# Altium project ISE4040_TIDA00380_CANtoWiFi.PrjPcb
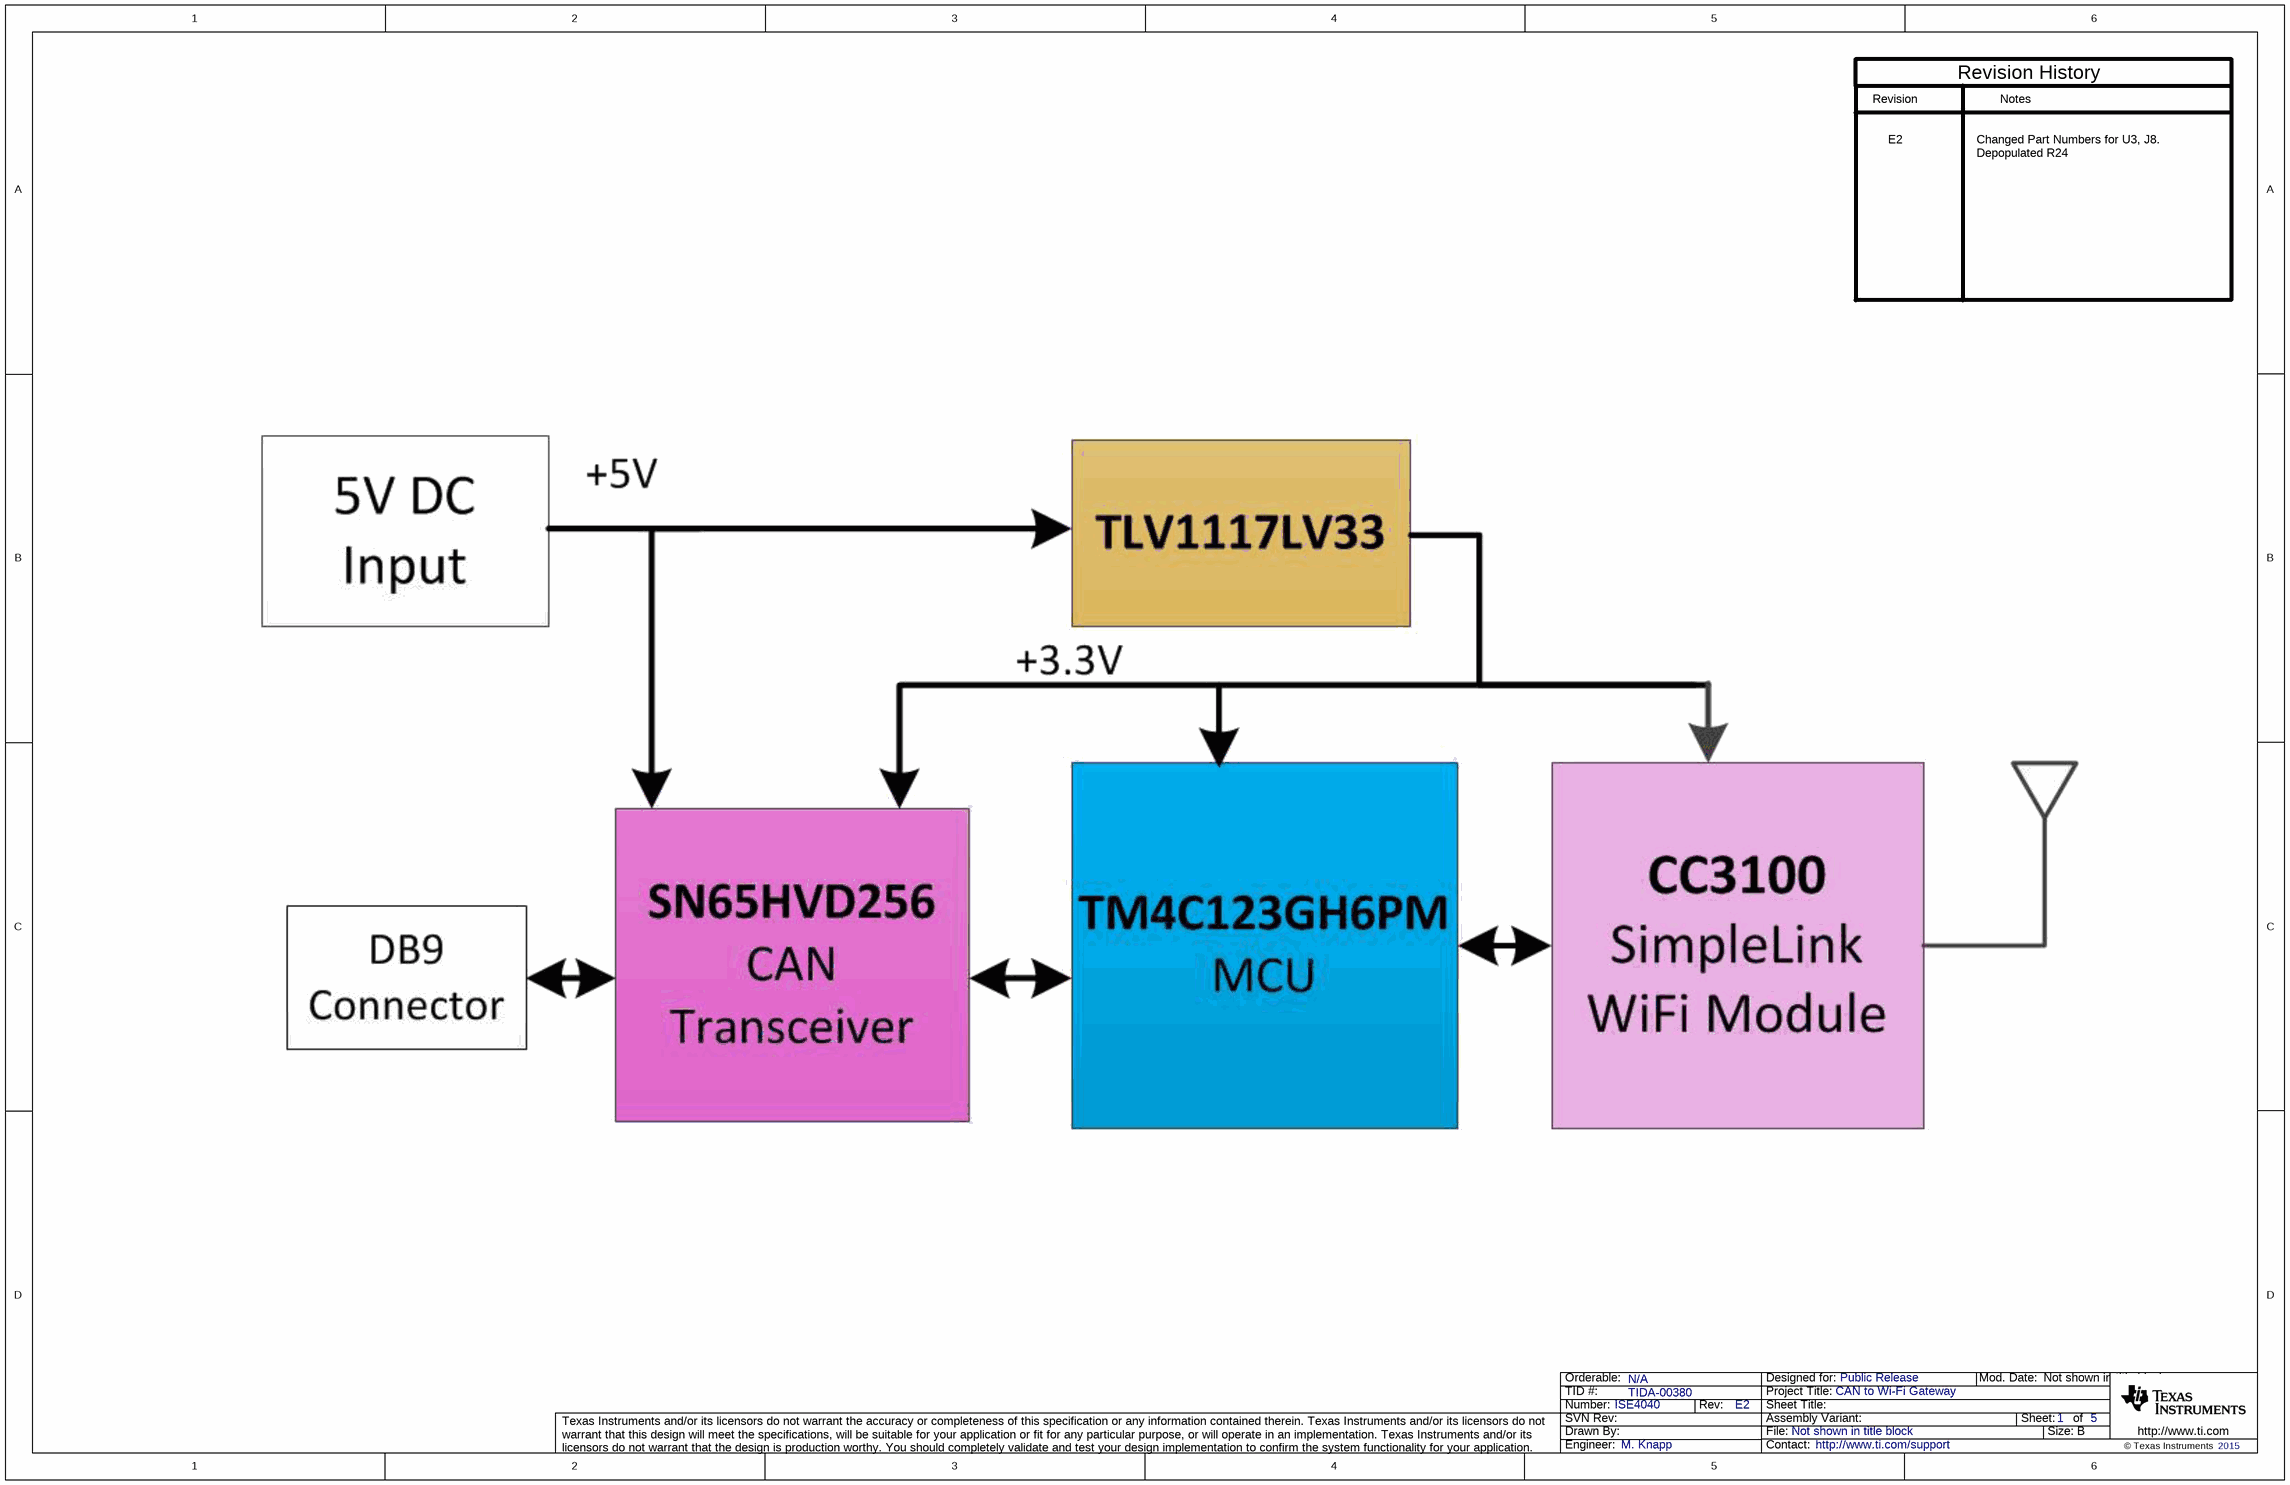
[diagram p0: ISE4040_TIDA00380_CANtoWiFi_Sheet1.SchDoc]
CopyrightYear: 2015; EVM_Orderable: N/A; PCB_Layout: Krypton Solution LLC; PCB_Rev: E2; PRJ_Customer: Public Release; PRJ_Engineer: M. Knapp; PRJ_Number: ISE4040; PRJ_Title: CAN to Wi-Fi Gateway; SCH_Rev: E2; TechSupport: http://www.ti.com/support; TID: TIDA-00380
5 sheets, 120 parts. Net scope: global (net labels, ports and power ports of the same name join across sheets).
Board file: ISE4040_TIDA00380_CANtoWiFi.PcbDoc
Sheets:
  ISE4040_TIDA00380_CANtoWiFi_Sheet1.SchDoc
  ISE4040_TIDA00380_CANtoWiFi_Sheet2.SchDoc
  ISE4040_TIDA00380_CANtoWiFi_Sheet3.SchDoc
  ISE4040_TIDA00380_CANtoWiFi_Sheet4.SchDoc
  ISE4040_TIDA00380_CANtoWiFi_Sheet5.SchDoc

## Sheet ISE4040_TIDA00380_CANtoWiFi_Sheet1.SchDoc
size 431 x 279 mm; Date: Not shown in title block; ApprovedBy: Not shown in title block; CheckedBy: Not shown in title block; Author: Not shown in title block; CompanyName: Not shown in title block; Engineer: Not shown in title block; Organization: Not shown in title block; Address1: Not shown in title block; Address2: Not shown in title block; Address3: Not shown in title block; Address4: Not shown in title block; DocumentNumber: 1; Revision: Use project parameter SCH_Rev; SheetNumber: 1; SheetTotal: 5; PageSetup: Record=PageOptions¦CenterHorizontal=True¦CenterVertical=True¦PrintScale=1.00¦XCorrection=1.00¦YCorrection=1.00¦PrintKind=0¦BorderSize=5000000¦LeftOffset=0¦BottomOffset=0¦Orientation=2¦PaperLength=1000¦PaperWidth=1000¦Scale=100¦PaperSource=15¦PrintQuality=600¦MediaType=1¦DitherType=10¦PaperKind=Letter¦PrintScaleMode=1

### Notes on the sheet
- Revision
- Notes
- Revision History
- E2
- Changed Part Numbers for U3, J8.
- Depopulated R24

## Sheet ISE4040_TIDA00380_CANtoWiFi_Sheet2.SchDoc
size 431 x 279 mm; Date: Not shown in title block; ApprovedBy: Not shown in title block; CheckedBy: Not shown in title block; Author: Not shown in title block; CompanyName: Not shown in title block; Engineer: Not shown in title block; Organization: Not shown in title block; Address1: Not shown in title block; Address2: Not shown in title block; Address3: Not shown in title block; Address4: Not shown in title block; DocumentNumber: 2; Revision: Use project parameter SCH_Rev; SheetNumber: 2; SheetTotal: 5; PageSetup: Record=PageOptions¦CenterHorizontal=True¦CenterVertical=True¦PrintScale=1.00¦XCorrection=1.00¦YCorrection=1.00¦PrintKind=0¦BorderSize=5000000¦LeftOffset=0¦BottomOffset=0¦Orientation=2¦PaperLength=1000¦PaperWidth=1000¦Scale=100¦PaperSource=15¦PrintQuality=600¦MediaType=1¦DitherType=10¦PaperKind=Letter¦PrintScaleMode=1
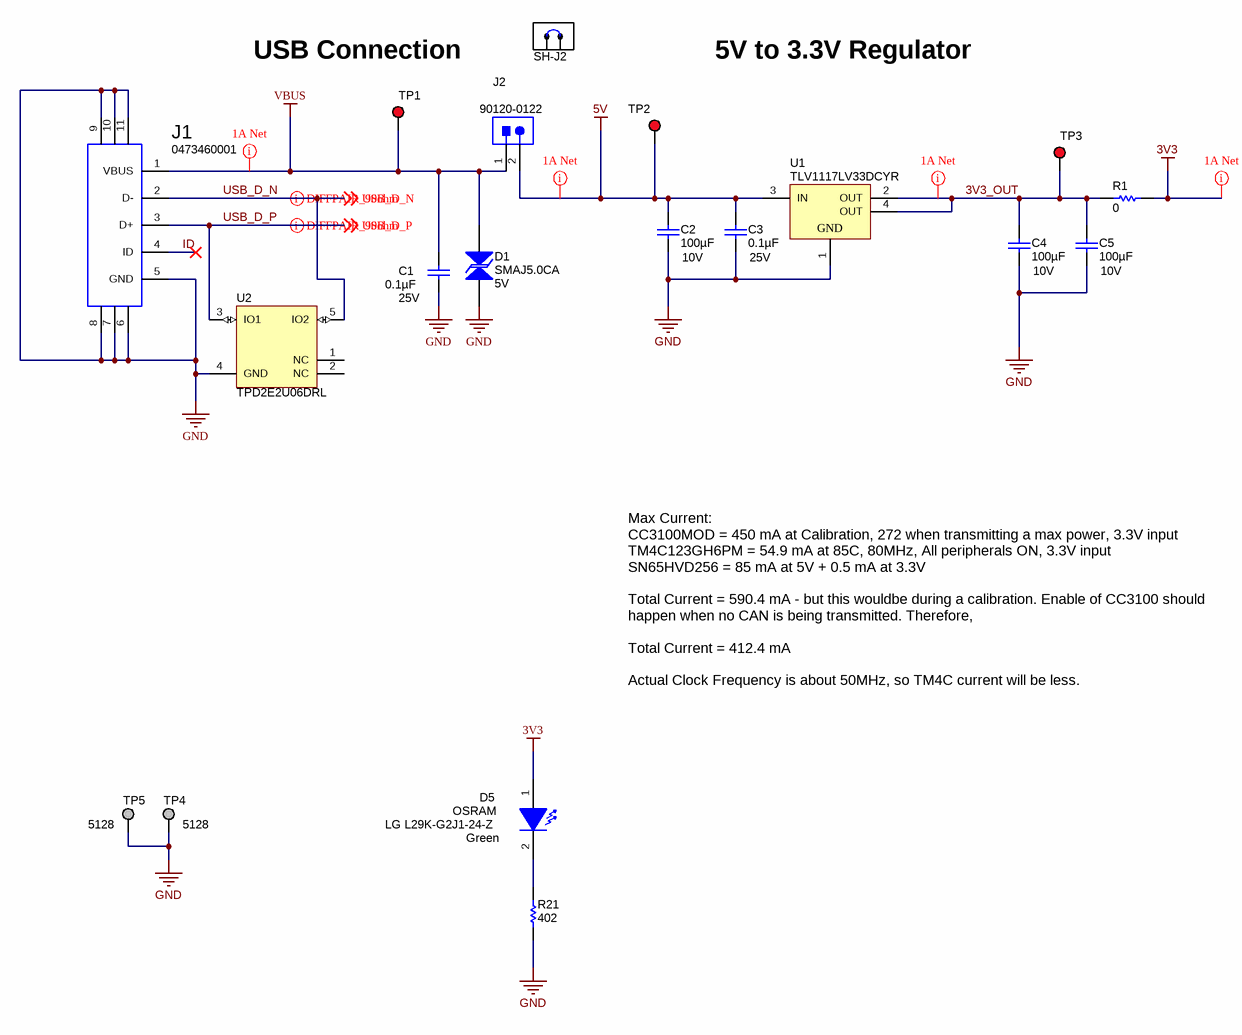
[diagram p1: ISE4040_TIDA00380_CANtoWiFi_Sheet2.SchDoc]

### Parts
C1  ValueDisplayed: 0.1µF  Value2: 25V  [0603]  (hidden comment: 06033C104JAT2A)
C2  ValueDisplayed: 100µF  Value2: 10V  [1210_280]  (hidden comment: C1210C107M8PACTU)
C3  ValueDisplayed: 0.1µF  Value2: 25V  [0603]  (hidden comment: 06033C104JAT2A)
C4  ValueDisplayed: 100µF  Value2: 10V  [1210_280]  (hidden comment: C1210C107M8PACTU)
C5  ValueDisplayed: 100µF  Value2: 10V  [1210_280]  (hidden comment: C1210C107M8PACTU)
D1  SMAJ5.0CA  value 5V  [SMA]
D5  value Green  Manufacturer: OSRAM  [LG L29K_GREEN]  (hidden comment: LG L29K-G2J1-24-Z)
J1  0473460001  [CONN_47346-0001]
J2  90120-0122  [CONN_90120-0122]
R1  ValueDisplayed: 0  [2010]  (hidden comment: CRCW20100000Z0EF)
R21  ValueDisplayed: 402  [0402]  (hidden comment: CRCW0402402RFKED)
SH-J2  2SN-BK-G  [2SN-BK-G]  (value not drawn)
TP1  5000  [Keystone5000]  (value not drawn)
TP2  5000  [Keystone5000]  (value not drawn)
TP3  5000  [Keystone5000]  (value not drawn)
TP4  5128  [Keystone5128]
TP5  5128  [Keystone5128]
U1  TLV1117LV33DCYR  [DCY0004A_N]
U2  TPD2E2U06DRL  [DRL0005A]

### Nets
3V3: D5.1(A) R1.2
5V: C2.1 C3.1 J2.2 TP2.1 U1.3(IN)
GND: C1.2 C2.2 C3.2 C4.2 C5.2 D1.2 J1.5(GND) J1.6 J1.7 J1.8 J1.9 J1.10 J1.11 R21.1 TP4.1 TP5.1 U1.1(GND) U2.4(GND)
VBUS: C1.1 D1.1 J1.1(VBUS) J2.1 TP1.1
3V3_OUT: C4.1 C5.1 R1.1 TP3.1 U1.2(OUT) U1.4(OUT)
ID: J1.4(ID)
USB_D_N: J1.2(D-) U2.5(IO2) ; off-sheet USB_D_N
USB_D_P: J1.3(D+) U2.3(IO1) ; off-sheet USB_D_P
NetD5_2: D5.2(K) R21.2

Not connected (* = marked no-connect by the designer): U2 1(NC) 2(NC)

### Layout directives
rule Width Constraint [Pref Width = 25mil    Min Width = 5mil    Max Width = 100mil]: 3V3, 3V3_OUT, 5V, VBUS
differential pair: USB_D_N, USB_D_P

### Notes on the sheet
- (near TP1) USB Connection
- 5V to 3.3V Regulator
- Max Current:
  CC3100MOD = 450 mA at Calibration, 272 when transmitting a max power, 3.3V input
  TM4C123GH6PM = 54.9 mA at 85C, 80MHz, All peripherals ON, 3.3V input
  SN65HVD256 = 85 mA at 5V + 0.5 mA at 3.3V
  Total Current = 590.4 mA - but this wouldbe during a calibration. Enable of CC3100 should
  happen when no CAN is being transmitted. Therefore,
  Total Current = 412.4 mA
  Actual Clock Frequency is about 50MHz, so TM4C current will be less.

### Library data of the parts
C1 = 06033C104JAT2A: CAP, CERM, 0.1 µF, 25 V, +/- 5%, X7R, 0603; Manufacturer: AVX; Polarized: N; CompType: Capacitor; Value: 0.1uF; U/M: EA; Cap_F: 0.0000001; Tolerance_%: 5; Value1: 0.05 ohm; VDC_V: 25; ESR_ohm: 0.05; TaMin_C: -55; TaMax_C: 125
C2 C4 C5 = C1210C107M8PACTU: CAP, CERM, 100 µF, 10 V, +/- 20%, X5R, 1210; Manufacturer: Wurth Elektronik; Polarized: N; CompType: Capacitor; Value: 100uF; U/M: EA; Cap_F: 0.0001; Tolerance_%: 20; Value1: Unknown; VDC_V: 10; TaMin_C: -55; TaMax_C: 85; Cap_Case: 1210
C3 = 06033C104JAT2A: CAP, CERM, 0.1 µF, 25 V, +/- 5%, X7R, 0603; Manufacturer: AVX; Polarized: N; CompType: Capacitor; Value: 0.1uF; U/M: EA; Cap_F: 0.0000001; Tolerance_%: 5; ESR_ohm: 0.05; Value1: 0.05 ohm; VDC_V: 25; TaMin_C: -55; TaMax_C: 125
D1 = SMAJ5.0CA: Diode, TVS, Bi, 5 V, 400 W, SMA; Manufacturer: Littelfuse; U/M: EA; Power_W: 400; Vr_V: 5; Value1: 400W; RJA_CperW: 120
D5 = LG L29K-G2J1-24-Z: LED, Green, SMD; Vf_V: 1.7; Value2: 1.7V; Io_A: 0.002; Tjmax_C: 110; Value1: W; U/M: EA
J1 = 0473460001: Connector, Receptacle, Micro-USB Type B, R/A, Bottom Mount SMT; Manufacturer: Molex; SymbolCreator: a0411947; U/M: EA
J2 = 90120-0122: Header, 100mil, 2x1, Tin, TH; Manufacturer: Molex; SymbolCreator: a0412235; U/M: EA
R1 = CRCW20100000Z0EF: RES, 0, 5%, 0.75 W, 2010; Manufacturer: Vishay-Dale; CompType: Resistor; Value: 0; Value_Code: 0000; Tolerance_%: 5; Power_W: 0.75; Value2: 0.75W; TempCo: ppm/C; EIA_Code: E24; U/M: EA
R21 = CRCW0402402RFKED: RES, 402, 1%, 0.063 W, 0402; Manufacturer: Vishay-Dale; CompType: Resistor; Value: 402; Value_Code: 402R; Tolerance_%: 1; Power_W: 0.063; Value2: 0.063W; VDC_V: 50; TempCo: 100 ppm/C; EIA_Code: E96; U/M: EA
SH-J2 = 2SN-BK-G: Shunt, 2mm, Gold plated, Black; Manufacturer: Samtec; Value: 1x2; Note: You can "mate" this to a header by matching the designator.  i.e. use SH-J3 for header J3
TP1-TP3 = 5000: Test Point, Miniature, Red, TH; Manufacturer: Keystone; CompType: Test Point Loop; U/M: EA
TP4 TP5 = 5128: Test Point, Multipurpose, Grey, TH; Manufacturer: Keystone; CompType: Test Point Loop; U/M: EA; SymbolCreator: a0412235
U1 = TLV1117LV33DCYR: Single Output LDO, 1 A, Fixed 3.3 V Output, 2 to 5.5 V Input, 4-pin SOT-223 (DCY), -40 to 125 degC, Green (RoHS & no Sb/Br); Manufacturer: Texas Instruments; Alternate Manufacturer: None; Alternate PartNumber: Equivalent; Accuracy(%): 2; Fixed Output Options(V): 3.3; Iout(Max)(A): 1; Iq(Typ)(mA): 0.05; SubFamily: Single Channel LDO; Vdo(Typ)(mV): 1200; Vin(Max)(V): 5.5
U2 = TPD2E2U06DRL: DUAL CHANNEL HIGH SPEED ESD PROTECTION DEVICE, DRL0005A; Manufacturer: Texas Instruments; SymbolCreator: a0411947; CompType: IC; U/M: EA

## Sheet ISE4040_TIDA00380_CANtoWiFi_Sheet3.SchDoc
size 431 x 279 mm; Date: Not shown in title block; ApprovedBy: Not shown in title block; CheckedBy: Not shown in title block; Author: Not shown in title block; CompanyName: Not shown in title block; Engineer: Not shown in title block; Organization: Not shown in title block; Address1: Not shown in title block; Address2: Not shown in title block; Address3: Not shown in title block; Address4: Not shown in title block; DocumentNumber: 3; Revision: Use project parameter SCH_Rev; SheetNumber: 3; SheetTotal: 5; PageSetup: Record=PageOptions¦CenterHorizontal=True¦CenterVertical=True¦PrintScale=1.00¦XCorrection=1.00¦YCorrection=1.00¦PrintKind=0¦BorderSize=5000000¦LeftOffset=0¦BottomOffset=0¦Orientation=2¦PaperLength=1000¦PaperWidth=1000¦Scale=100¦PaperSource=15¦PrintQuality=600¦MediaType=1¦DitherType=10¦PaperKind=Letter¦PrintScaleMode=1
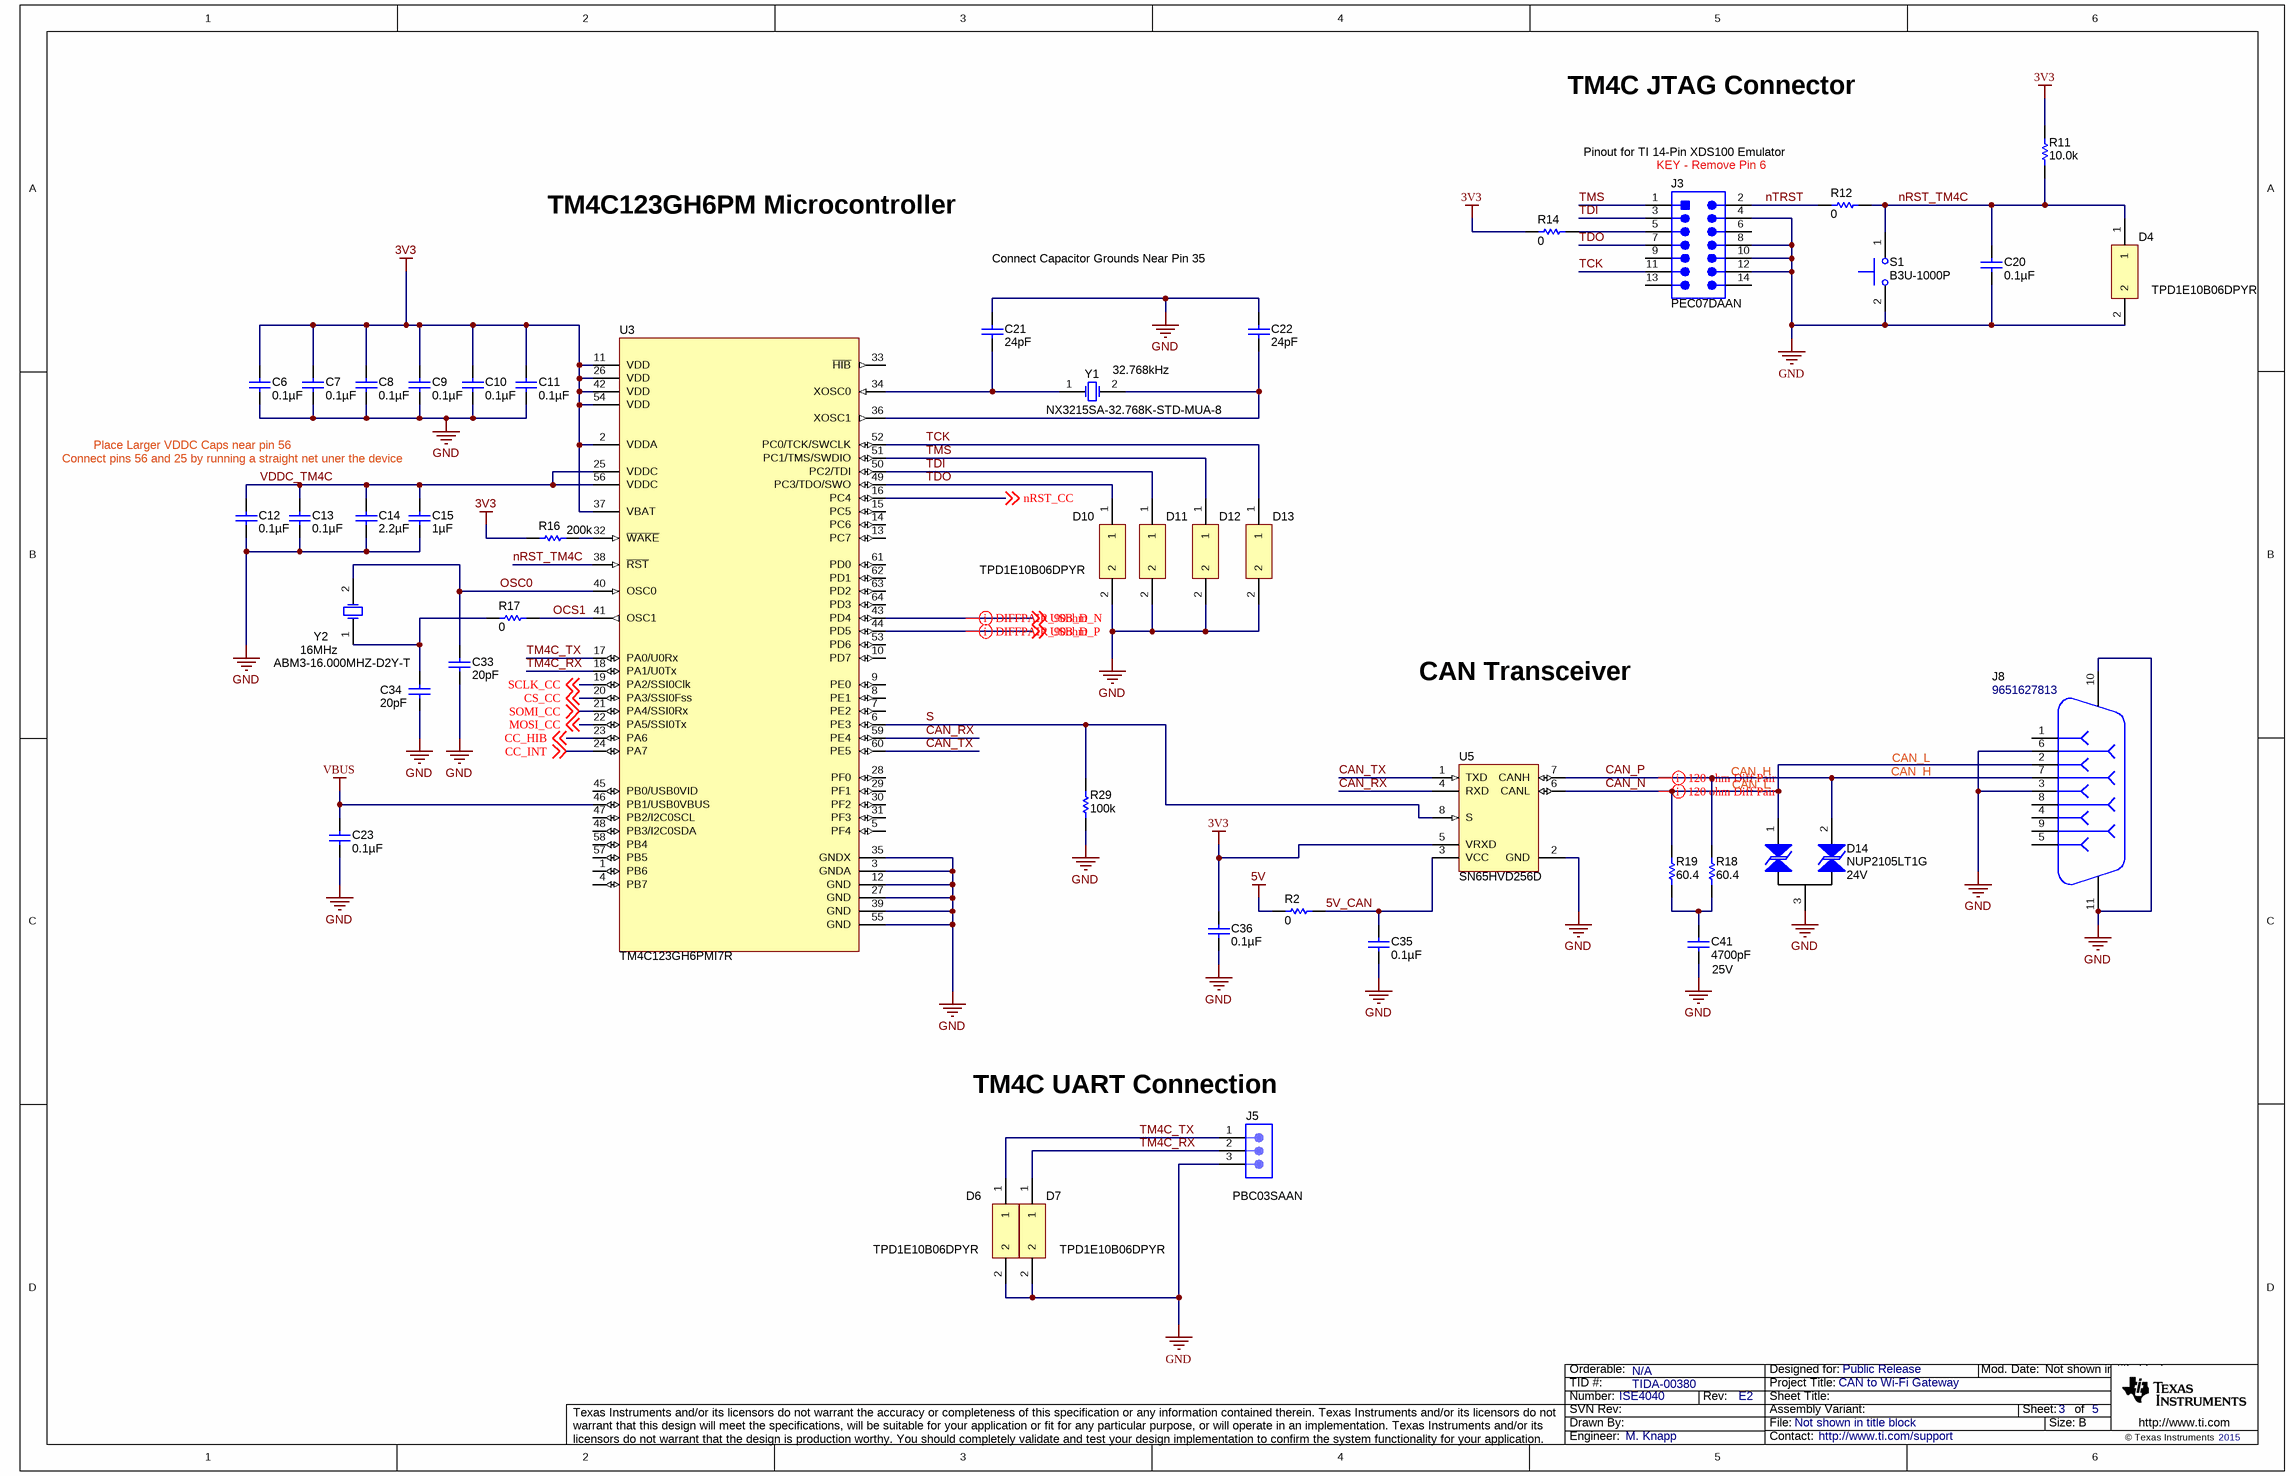
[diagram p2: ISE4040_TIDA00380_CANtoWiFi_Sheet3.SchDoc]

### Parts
C6  ValueDisplayed: 0.1µF  [0402]  (hidden comment: GRM155R71C104KA88D)
C7  ValueDisplayed: 0.1µF  [0402]  (hidden comment: GRM155R71C104KA88D)
C8  ValueDisplayed: 0.1µF  [0402]  (hidden comment: GRM155R71C104KA88D)
C9  ValueDisplayed: 0.1µF  [0402]  (hidden comment: GRM155R71C104KA88D)
C10  ValueDisplayed: 0.1µF  [0402]  (hidden comment: GRM155R71C104KA88D)
C11  ValueDisplayed: 0.1µF  [0402]  (hidden comment: GRM155R71C104KA88D)
C12  ValueDisplayed: 0.1µF  [0402]  (hidden comment: GRM155R71C104KA88D)
C13  ValueDisplayed: 0.1µF  [0402]  (hidden comment: GRM155R71C104KA88D)
C14  ValueDisplayed: 2.2µF  [0805_HV]  (hidden comment: C0805C225K8RACTU)
C15  ValueDisplayed: 1µF  [0603]  (hidden comment: GRM188R71C105KA12D)
C20  ValueDisplayed: 0.1µF  [0402]  (hidden comment: GRM155R71C104KA88D)
C21  ValueDisplayed: 24pF  [0402]  (hidden comment: GRM1555C1H240JA01D)
C22  ValueDisplayed: 24pF  [0402]  (hidden comment: GRM1555C1H240JA01D)
C23  ValueDisplayed: 0.1µF  [0402]  (hidden comment: GRM155R71C104KA88D)
C33  ValueDisplayed: 20pF  [0603]  (hidden comment: GRM1885C1H200JA01D)
C34  ValueDisplayed: 20pF  [0603]  (hidden comment: GRM1885C1H200JA01D)
C35  ValueDisplayed: 0.1µF  [0402]  (hidden comment: GRM155R71C104KA88D)
C36  ValueDisplayed: 0.1µF  [0402]  (hidden comment: GRM155R71C104KA88D)
C41  ValueDisplayed: 4700pF  Value2: 25V  [0402]  (hidden comment: C1005X7R1E472K)
D4  TPD1E10B06DPYR  [DPY0002A]
D6  TPD1E10B06DPYR  [DPY0002A]
D7  TPD1E10B06DPYR  [DPY0002A]
D10  TPD1E10B06DPYR  [DPY0002A]
D11  TPD1E10B06DPYR  [DPY0002A]  (value not drawn)
D12  TPD1E10B06DPYR  [DPY0002A]  (value not drawn)
D13  TPD1E10B06DPYR  [DPY0002A]  (value not drawn)
D14  NUP2105LT1G  value 24V  [SOT-23]
J3  PEC07DAAN  [CONN_PEC07DAAN]
J5  PBC03SAAN  [PBC03SAAN]
J8  9651627813  [Harting_09 65 162 6810]
R2  ValueDisplayed: 0  [0402]  (hidden comment: CRCW04020000Z0ED)
R11  ValueDisplayed: 10.0k  [0402]  (hidden comment: CRCW040210K0FKED)
R12  ValueDisplayed: 0  [0402]  (hidden comment: CRCW04020000Z0ED)
R14  ValueDisplayed: 0  [0402]  (hidden comment: CRCW04020000Z0ED)
R16  ValueDisplayed: 200k  [0402]  (hidden comment: CRCW0402200KFKED)
R17  ValueDisplayed: 0  [0402]  (hidden comment: CRCW04020000Z0ED)
R18  ValueDisplayed: 60.4  [0603]  (hidden comment: CRCW060360R4FKEA)
R19  ValueDisplayed: 60.4  [0603]  (hidden comment: CRCW060360R4FKEA)
R29  ValueDisplayed: 100k  [0402]  (hidden comment: CRCW0402100KFKED)
S1  B3U-1000P  [SW_B3U-1000P]
U3  TM4C123GH6PMI7R  [PM0064A_N]
U5  SN65HVD256D  [D0008A_L]
Y1  NX3215SA-32.768K-STD-MUA-8  Frequency: 32.768kHz  [XTAL_NX3215SA]
Y2  ABM3-16.000MHZ-D2Y-T  Frequency: 16MHz  [XTAL_ABM3]

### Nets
3V3: C6.1 C7.1 C8.1 C9.1 C10.1 C11.1 C36.1 R11.2 R14.2 R16.1 U3.2(VDDA) U3.11(VDD) U3.26(VDD) U3.37(VBAT) U3.42(VDD) U3.54(VDD) U5.5(VRXD)
5V: R2.2
GND: C6.2 C7.2 C8.2 C9.2 C10.2 C11.2 C12.2 C13.2 C14.2 C15.2 C20.2 C21.1 C22.1 C23.2 C33.2 C34.2 C35.2 C36.2 C41.2 D4.2 D6.2 D7.2 D10.2 D11.2 D12.2 D13.2 D14.3 J3.4 J3.8 J3.10 J3.12 J5.3 J8.3 J8.6 J8.10 J8.11 R29.1 S1.2 U3.3(GNDA) U3.12(GND) U3.27(GND) U3.35(GNDX) U3.39(GND) U3.55(GND) U5.2(GND)
VBUS: C23.1 U3.46(PB1/USB0VBUS)
5V_CAN: C35.1 R2.1 U5.3(VCC)
CAN_N: D14.1 J8.2 R19.2 U5.6(CANL)
CAN_P: D14.2 J8.7 R18.2 U5.7(CANH)
CAN_RX: U3.59(PE4) U5.4(RXD)
CAN_TX: U3.60(PE5) U5.1(TXD)
CC_HIB: U3.23(PA6) ; off-sheet CC_HIB
CC_INT: U3.24(PA7) ; off-sheet CC_INT
CS_CC: U3.20(PA3/SSI0Fss) ; off-sheet CS_CC
MOSI_CC: U3.22(PA5/SSI0Tx) ; off-sheet MOSI_CC
nRST_CC: U3.16(PC4) ; off-sheet nRST_CC
nRST_TM4C: C20.1 D4.1 R11.1 R12.1 S1.1 U3.38(~{RST})
nTRST: J3.2 R12.2
OCS1: R17.2 U3.41(OSC1)
OSC0: C33.1 U3.40(OSC0) Y2.2(OSC2)
S: R29.2 U3.6(PE3) U5.8(S)
SCLK_CC: U3.19(PA2/SSI0Clk) ; off-sheet SCLK_CC
SOMI_CC: U3.21(PA4/SSI0Rx) ; off-sheet SOMI_CC
TCK: D13.1 J3.11 U3.52(PC0/TCK/SWCLK)
TDI: D11.1 J3.3 U3.50(PC2/TDI)
TDO: D10.1 J3.7 U3.49(PC3/TDO/SWO)
TM4C_RX: D7.1 J5.2 U3.18(PA1/U0Tx)
TM4C_TX: D6.1 J5.1 U3.17(PA0/U0Rx)
TMS: D12.1 J3.1 U3.51(PC1/TMS/SWDIO)
USB_D_N: U3.43(PD4) ; off-sheet USB_D_N
USB_D_P: U3.44(PD5) ; off-sheet USB_D_P
VDDC_TM4C: C12.1 C13.1 C14.1 C15.1 U3.25(VDDC) U3.56(VDDC)
NetC21_2: C21.2 U3.34(XOSC0) Y1.1(OSC1)
NetC22_2: C22.2 U3.36(XOSC1) Y1.2(OSC2)
NetC34_1: C34.1 R17.1 Y2.1(OSC1)
NetC41_1: C41.1 R18.1 R19.1
NetJ3_5: J3.5 R14.1
NetR16_2: R16.2 U3.32(~{WAKE})

Not connected (* = marked no-connect by the designer): J3 6 9 13 14; J8 1 4 5 8 9; U3 1(PB6) 4(PB7) 5(PF4) 7(PE2) 8(PE1) 9(PE0) 10(PD7) 13(PC7) 14(PC6) 15(PC5) 28(PF0) 29(PF1) 30(PF2) 31(PF3) 33(~{HIB}) 45(PB0/USB0VID) 47(PB2/I2C0SCL) 48(PB3/I2C0SDA) 53(PD6) 57(PB5) 58(PB4) 61(PD0) 62(PD1) 63(PD2) 64(PD3)

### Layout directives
differential pair: CAN_N, CAN_P, USB_D_N, USB_D_P

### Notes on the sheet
- TM4C JTAG Connector
- Pinout for TI 14-Pin XDS100 Emulator
- (near J3) KEY - Remove Pin 6
- TM4C123GH6PM Microcontroller
- Connect Capacitor Grounds Near Pin 35
- Place Larger VDDC Caps near pin 56
- Connect pins 56 and 25 by running a straight net uner the device
- CAN Transceiver
- CAN_L
- CAN_H
- (near J5) TM4C UART Connection

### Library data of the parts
C6-C13 C20 C23 C35 C36 = GRM155R71C104KA88D: CAP, CERM, 0.1 µF, 16 V, +/- 10%, X7R, 0402; Manufacturer: MuRata; Polarized: N; CompType: Capacitor; Value: 0.1uF; U/M: EA; Cap_F: 0.0000001; Tolerance_%: 10; Value1: Unknown; VDC_V: 16; Value2: 16V; TaMin_C: -55; TaMax_C: 125
C14 = C0805C225K8RACTU: CAP, CERM, 2.2 µF, 10 V, +/- 10%, X7R, 0805; Manufacturer: Kemet; Polarized: N; CompType: Capacitor; Value: 2.2uF; U/M: EA; Cap_F: 0.0000022; Tolerance_%: 10; ESR_ohm: 0.008; Value1: 0.008 ohm; Value2: 10V; IRMS_A: 15.55; TaMin_C: -55; TaMax_C: 125; Cap_Case: 0805
C15 = GRM188R71C105KA12D: CAP, CERM, 1 µF, 16 V, +/- 10%, X7R, 0603; Manufacturer: MuRata; Polarized: N; CompType: Capacitor; Value: 1uF; U/M: EA; Cap_F: 0.000001; Tolerance_%: 10; ESR_ohm: 0.011; Value1: 0.011 ohm; VDC_V: 16; Value2: 16V; TaMin_C: -55; TaMax_C: 125
C21 C22 = GRM1555C1H240JA01D: CAP, CERM, 24 pF, 50 V, +/- 5%, C0G/NP0, 0402; Manufacturer: MuRata; Polarized: N; CompType: Capacitor; Value: 24pF; U/M: EA; Cap_F: 0.000000000024; Tolerance_%: 5; Value1: Unknown; VDC_V: 50; Value2: 50V; TaMin_C: -55; TaMax_C: 125
C33 C34 = GRM1885C1H200JA01D: CAP, CERM, 20 pF, 50 V, +/- 5%, C0G/NP0, 0603; Manufacturer: MuRata; Polarized: N; CompType: Capacitor; Value: 20pF; U/M: EA; Cap_F: 0.00000000002; Tolerance_%: 5; Value1: Unknown; VDC_V: 50; Value2: 50V; TaMin_C: -55; TaMax_C: 125
C41 = C1005X7R1E472K: CAP, CERM, 4700 pF, 25 V, +/- 10%, X7R, 0402; Manufacturer: TDK; Polarized: N; CompType: Capacitor; Value: 4700pF; U/M: EA; Cap_F: 0.0000000047; Tolerance_%: 10; ESR_ohm: 0.0826; Value1: 0.0826 ohm; VDC_V: 25; TaMin_C: -55; TaMax_C: 125
D4 D6 D7 D10-D13 = TPD1E10B06DPYR: ESD in 0402 Package with 10 pF Capacitance and 6 V Breakdown, 1 Channel, -40 to +125 degC, 2-pin X2SON (DPY), Green (RoHS & no Sb/Br); Manufacturer: Texas Instruments; Alternate Manufacturer: None; Alternate PartNumber: Equivalent; Breakdown Voltage(Min)(V): 6; Eco-Plan: TBD; IEC 61000-4-2 Air-Gap(+/- kV): 30; IO Capacitance(Typ)(pF): 10; SubFamily: ESD Solution
D14 = NUP2105LT1G: Diode, TVS, Bi, 24 V, 350 W, SOT-23; Manufacturer: ON Semiconductor; SymbolCreator: a0411947; U/M: EA; Power_W: 350; Vr_V: 24; Value1: 350W
J3 = PEC07DAAN: Header, 100mil, 7x2, Tin, TH; Manufacturer: Sullins Connector Solutions; SymbolCreator: a0412235; U/M: EA
J5 = PBC03SAAN: Header, 100mil, 3x1, Gold, TH; Manufacturer: Sullins Connector Solutions; U/M: EA; Value: 1x3
J8 = 9651627813: D-Sub-9, 11Pos, Female, TH; Manufacturer: Harting; SymbolCreator: x0208326; CompType: D-Sub; U/M: EA
R2 R12 R14 R17 = CRCW04020000Z0ED: RES, 0, 5%, 0.063 W, 0402; Manufacturer: Vishay-Dale; CompType: Resistor; Value: 0; Value_Code: 0000; Tolerance_%: 5; Power_W: 0.063; Value2: 0.063W; VDC_V: 50; TempCo: 200 ppm/C; EIA_Code: E24; U/M: EA
R11 = CRCW040210K0FKED: RES, 10.0 k, 1%, 0.063 W, 0402; Manufacturer: Vishay-Dale; CompType: Resistor; Value: 10.0k; Res_ohm: 10000; Value_Code: 10k0; Tolerance_%: 1; Power_W: 0.063; Value2: 0.063W; VDC_V: 50; TempCo: 100 ppm/C; EIA_Code: E96; U/M: EA
R16 = CRCW0402200KFKED: RES, 200 k, 1%, 0.063 W, 0402; Manufacturer: Vishay-Dale; CompType: Resistor; Value: 200k; Res_ohm: 200000; Tolerance_%: 1; Power_W: 0.063; Value2: 0.063W; VDC_V: 50; TempCo: 100 ppm/C; EIA_Code: E96; U/M: EA
R18 R19 = CRCW060360R4FKEA: RES, 60.4, 1%, 0.1 W, 0603; Manufacturer: Vishay-Dale; CompType: Resistor; Value: 60.4; Value_Code: 60R4; Tolerance_%: 1; Power_W: 0.1; Value2: 0.1W; VDC_V: 75; TempCo: 100 ppm/C; EIA_Code: E96; U/M: EA
R29 = CRCW0402100KFKED: RES, 100 k, 1%, 0.063 W, 0402; Manufacturer: Vishay-Dale; CompType: Resistor; Value: 100k; Res_ohm: 100000; Tolerance_%: 1; Power_W: 0.063; Value2: 0.063W; VDC_V: 50; TempCo: 100 ppm/C; EIA_Code: E96; U/M: EA
S1 = B3U-1000P: SWITCH TACTILE SPST-NO 0.05A 12V; Manufacturer: Omron Electronic Components; SymbolCreator: a0412235; VDC_V: 12; SwitchFunction: Off-Mom; PositionCount: 1; CurrentRating_mA: 50
U3 = TM4C123GH6PMI7R: Tiva C Series Microcontroller, PM0064A; Manufacturer: Texas Instruments; SymbolCreator: x0208326; CompType: IC; U/M: EA
U5 = SN65HVD256D: CAN Transceiver with Fast Loop Times for Highly Loaded Networks, 85 mA, 5 V, -40 to 125 degC, 8-pin SOIC (D), Green (RoHS & no Sb/Br); Manufacturer: Texas Instruments; Alternate Manufacturer: None; Alternate PartNumber: Equivalent; Drivers Per Package: 1; Bus Fault Voltage(V): -27 to 40; ICC(Max)(mA): 85; Supply Voltage(s)(V): 5; Rating: Catalog
Y1 = NX3215SA-32.768K-STD-MUA-8: Crystal, 32.768kHz, 12.5pF, SMD; Manufacturer: NDK; SymbolCreator: a0412235; U/M: EA; TaMin_C: -40; TaMax_C: 85; Frequency Stability: ±20ppm
Y2 = ABM3-16.000MHZ-D2Y-T: Crystal, 16 MHz, 18 pF, SMD; Manufacturer: Abracon Corportation; SymbolCreator: a0412235; U/M: EA; TaMin_C: -40; TaMax_C: 85; Frequency Stability: ±30ppm

## Sheet ISE4040_TIDA00380_CANtoWiFi_Sheet4.SchDoc
size 431 x 279 mm; Date: Not shown in title block; ApprovedBy: Not shown in title block; CheckedBy: Not shown in title block; Author: Not shown in title block; CompanyName: Not shown in title block; Engineer: Not shown in title block; Organization: Not shown in title block; Address1: Not shown in title block; Address2: Not shown in title block; Address3: Not shown in title block; Address4: Not shown in title block; DocumentNumber: 4; Revision: Use project parameter SCH_Rev; SheetNumber: 4; SheetTotal: 5; PageSetup: Record=PageOptions¦CenterHorizontal=True¦CenterVertical=True¦PrintScale=1.00¦XCorrection=1.00¦YCorrection=1.00¦PrintKind=0¦BorderSize=5000000¦LeftOffset=0¦BottomOffset=0¦Orientation=2¦PaperLength=1000¦PaperWidth=1000¦Scale=100¦PaperSource=15¦PrintQuality=600¦MediaType=1¦DitherType=10¦PaperKind=Letter¦PrintScaleMode=1
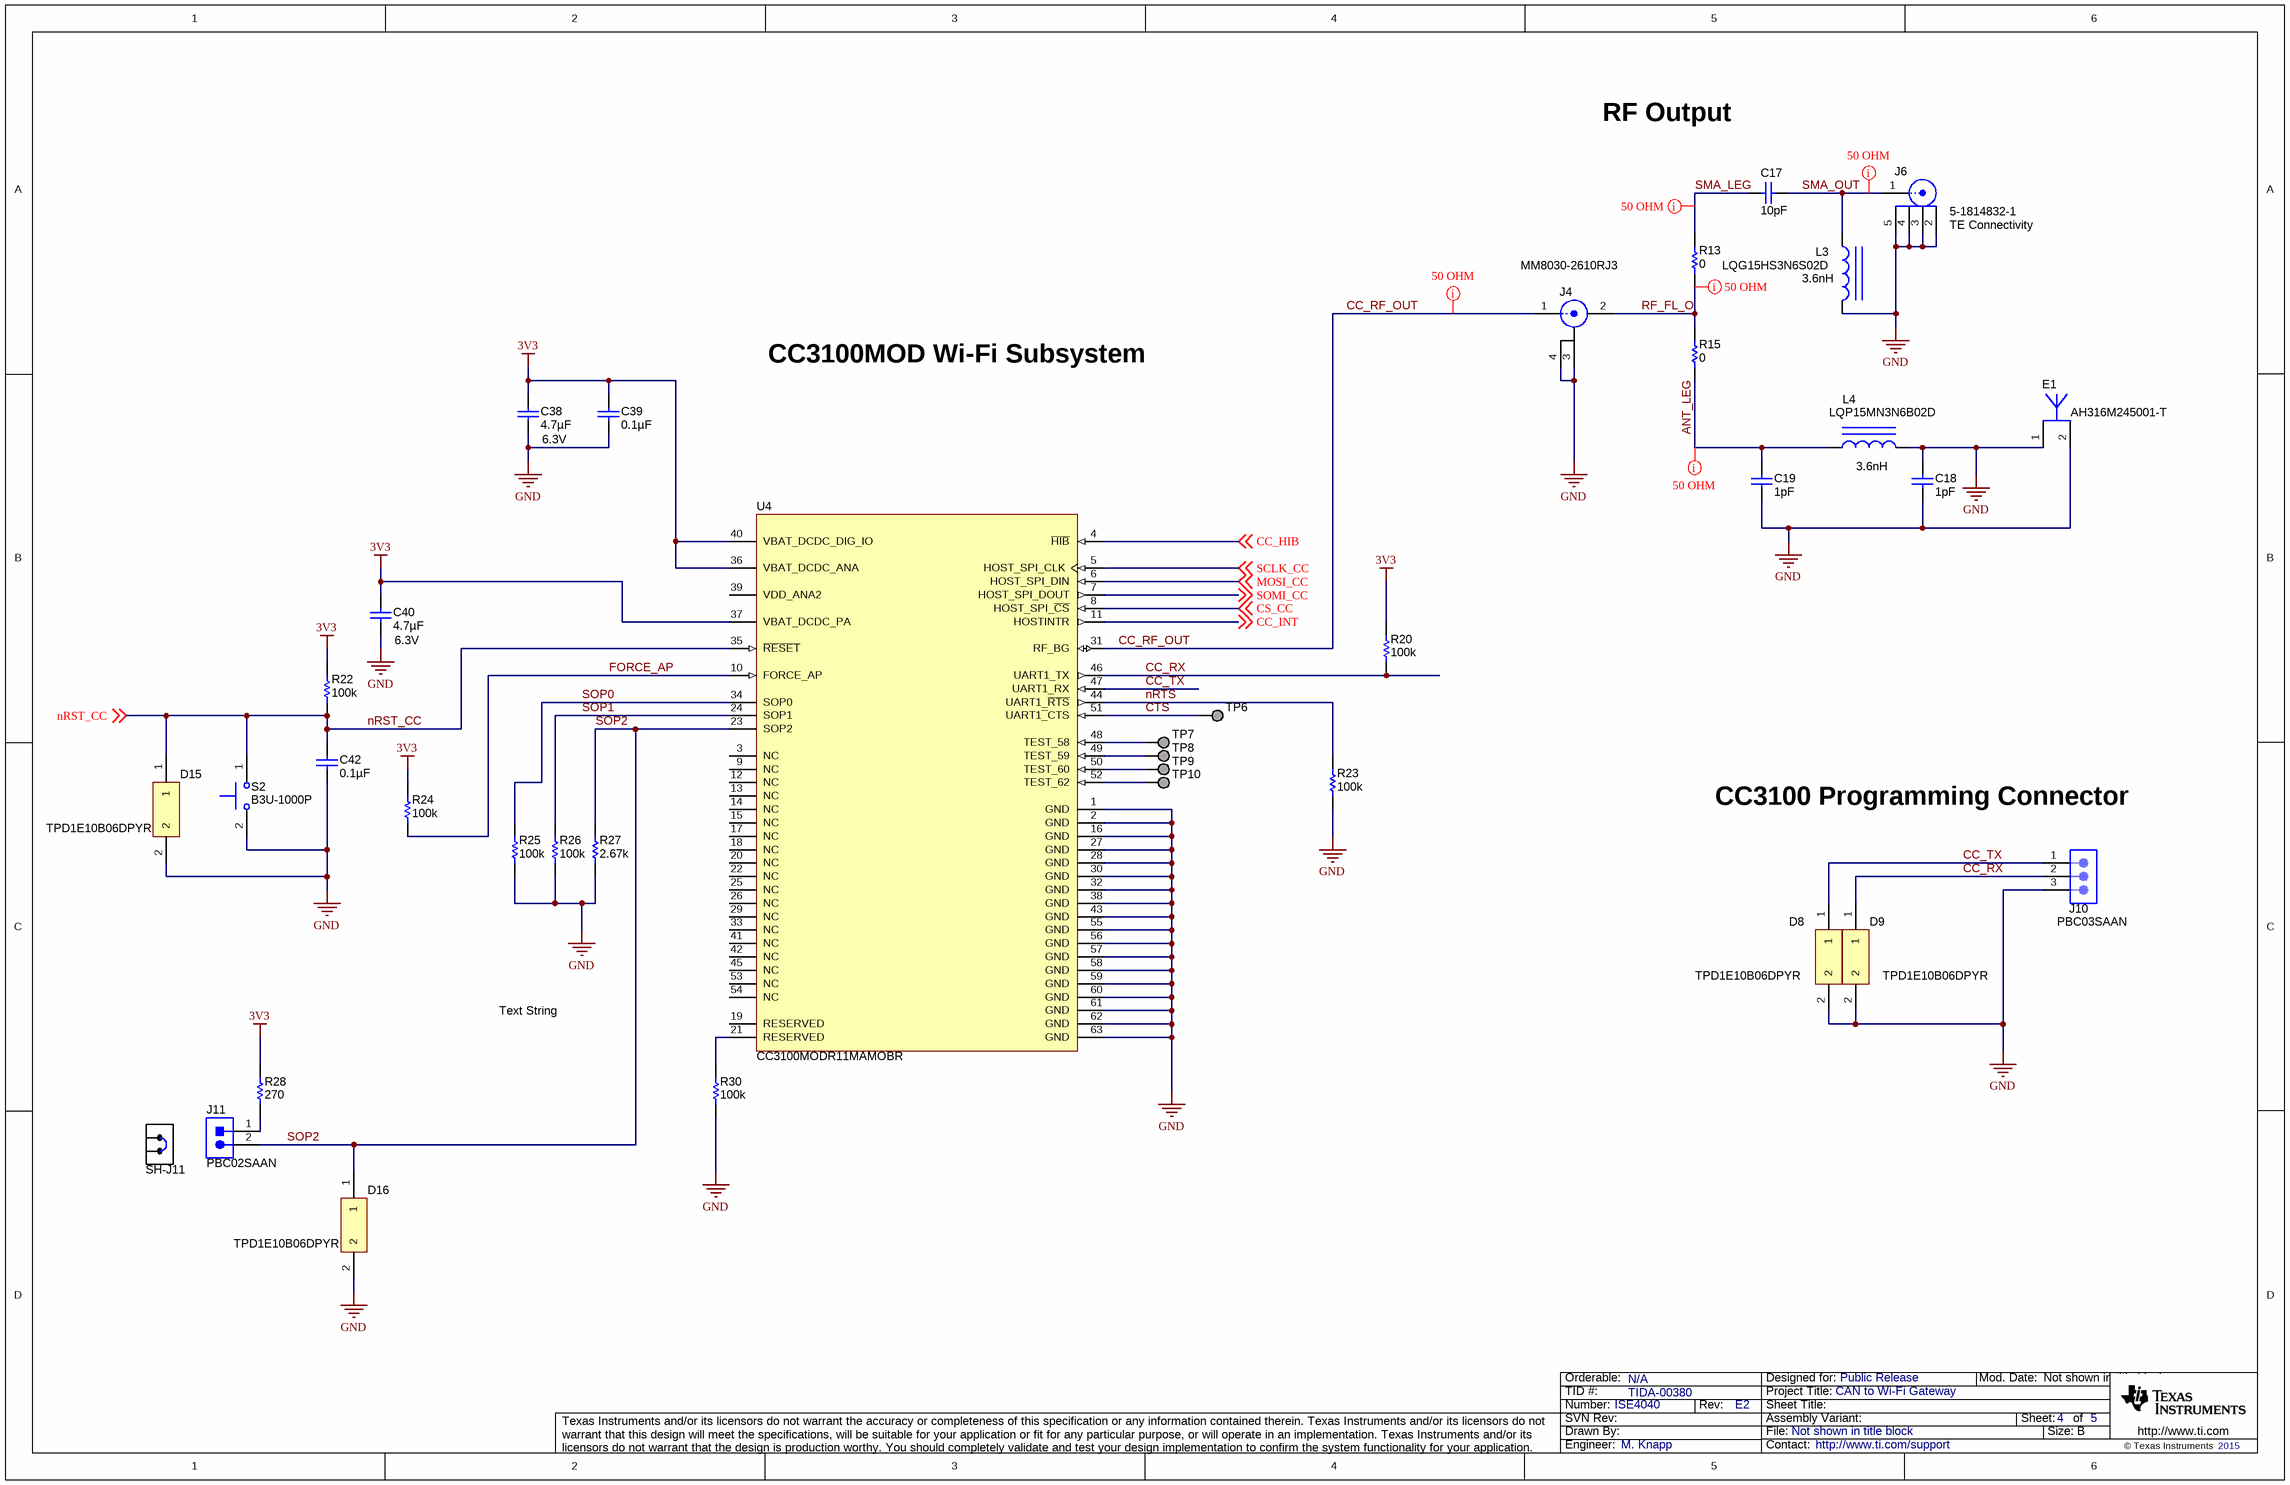
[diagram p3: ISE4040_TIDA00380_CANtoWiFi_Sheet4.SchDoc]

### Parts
C17  ValueDisplayed: 10pF  [0402L]  (hidden comment: GRM1555C1H100JA01D)
C18  ValueDisplayed: 1pF  [0402L]  (hidden comment: GRM1555C1H1R0BA01D)
C19  ValueDisplayed: 1pF  [0402L]  (hidden comment: GRM1555C1H1R0BA01D)
C38  ValueDisplayed: 4.7µF  Value2: 6.3V  [0402]  (hidden comment: GRM155R60J475ME87D)
C39  ValueDisplayed: 0.1µF  [0402]  (hidden comment: GRM155R71C104KA88D)
C40  ValueDisplayed: 4.7µF  Value2: 6.3V  [0402]  (hidden comment: GRM155R60J475ME87D)
C42  ValueDisplayed: 0.1µF  [0402]  (hidden comment: GRM155R71C104KA88D)
D8  TPD1E10B06DPYR  [DPY0002A]
D9  TPD1E10B06DPYR  [DPY0002A]
D15  TPD1E10B06DPYR  [DPY0002A]
D16  TPD1E10B06DPYR  [DPY0002A]
E1  AH316M245001-T  [TAYO_AH316M]
J4  MM8030-2610RJ3  [MuRata_MM8030-2610]
J6  5-1814832-1  Manufacturer: TE Connectivity  [TE_5-1814832-1]
J10  PBC03SAAN  [PBC03SAAN]
J11  PBC02SAAN  [Sullins_PBC02SAAN]
L3  LQG15HS3N6S02D  value 3.6nH  [IND_LQG15H]
L4  LQP15MN3N6B02D  value 3.6nH  [LQP_0402]
R13  ValueDisplayed: 0  [0402L]  (hidden comment: CRCW04020000Z0ED)
R15  ValueDisplayed: 0  [0402L]  (hidden comment: CRCW04020000Z0ED)
R20  ValueDisplayed: 100k  [0402]  (hidden comment: CRCW0402100KFKED)
R22  ValueDisplayed: 100k  [0402]  (hidden comment: CRCW0402100KFKED)
R23  ValueDisplayed: 100k  [0402]  (hidden comment: CRCW0402100KFKED)
R24  ValueDisplayed: 100k  [0402]  (hidden comment: CRCW0402100KFKED)
R25  ValueDisplayed: 100k  [0402]  (hidden comment: CRCW0402100KFKED)
R26  ValueDisplayed: 100k  [0402]  (hidden comment: CRCW0402100KFKED)
R27  ValueDisplayed: 2.67k  [0402]  (hidden comment: CRCW04022K67FKED)
R28  ValueDisplayed: 270  [0402]  (hidden comment: CRCW0402270RJNED)
R30  ValueDisplayed: 100k  [0402]  (hidden comment: CRCW0402100KFKED)
S2  B3U-1000P  [SW_B3U-1000P]
SH-J11  2SN-BK-G  [2SN-BK-G]  (value not drawn)
TP6  Pogo Pad  [PogoPad]  (value not drawn)  (no BOM)
TP7  Pogo Pad  [PogoPad]  (value not drawn)  (no BOM)
TP8  Pogo Pad  [PogoPad]  (value not drawn)  (no BOM)
TP9  Pogo Pad  [PogoPad]  (value not drawn)  (no BOM)
TP10  Pogo Pad  [PogoPad]  (value not drawn)  (no BOM)
U4  CC3100MODR11MAMOBR  [MOB0063A]

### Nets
3V3: C38.1 C39.1 C40.1 R20.2 R22.2 R24.2 R28.2 U4.36(VBAT_DCDC_ANA) U4.37(VBAT_DCDC_PA) U4.40(VBAT_DCDC_DIG_IO)
GND: C18.1 C18.2 C19.2 C38.2 C39.2 C40.2 C42.2 D8.2 D9.2 D15.2 D16.2 E1.1 E1.2 J4.3(GND) J4.4(GND) J6.2 J6.3 J6.4 J6.5 J10.3 L3.1 L4.2 R23.1 R25.1 R26.1 R27.1 R30.1 S2.2 U4.1(GND) U4.2(GND) U4.16(GND) U4.27(GND) U4.28(GND) U4.30(GND) U4.32(GND) U4.38(GND) U4.43(GND) U4.55(GND) U4.56(GND) U4.57(GND) U4.58(GND) U4.59(GND) U4.60(GND) U4.61(GND) U4.62(GND) U4.63(GND)
ANT_LEG: C19.1 L4.1 R15.1
CC_HIB: U4.4(~{HIB}) ; off-sheet CC_HIB
CC_INT: U4.11(HOSTINTR) ; off-sheet CC_INT
CC_RF_OUT: J4.1(IN) U4.31(RF_BG)
CC_RX: D9.1 J10.2 R20.1 U4.46(UART1_TX)
CC_TX: D8.1 J10.1 U4.47(UART1_RX)
CS_CC: U4.8(HOST_SPI_~{CS}) ; off-sheet CS_CC
CTS: TP6.1 U4.51(UART1~{_}CTS)
FORCE_AP: R24.1 U4.10(FORCE_AP)
MOSI_CC: U4.6(HOST_SPI_DIN) ; off-sheet MOSI_CC
nRST_CC: C42.1 D15.1 R22.1 S2.1 U4.35(~{RESET}) ; off-sheet nRST_CC
nRTS: R23.2 U4.44(UART1_~{RTS})
RF_FL_O: J4.2(OUT) R13.1 R15.2
SCLK_CC: U4.5(HOST_SPI_CLK) ; off-sheet SCLK_CC
SMA_LEG: C17.2 R13.2
SMA_OUT: C17.1 J6.1 L3.2
SOMI_CC: U4.7(HOST_SPI_DOUT) ; off-sheet SOMI_CC
SOP0: R25.2 U4.34(SOP0)
SOP1: R26.2 U4.24(SOP1)
SOP2: D16.1 J11.2 R27.2 U4.23(SOP2)
NetJ11_1: J11.1 R28.1
NetR30_2: R30.2 U4.21(RESERVED)
NetTP7_1: TP7.1 U4.48(TEST_58)
NetTP8_1: TP8.1 U4.49(TEST_59)
NetTP9_1: TP9.1 U4.50(TEST_60)
NetTP10_1: TP10.1 U4.52(TEST_62)

Not connected (* = marked no-connect by the designer): U4 3(NC) 9(NC) 12(NC) 13(NC) 14(NC) 15(NC) 17(NC) 18(NC) 19(RESERVED) 20(NC) 22(NC) 25(NC) 26(NC) 29(NC) 33(NC) 39(VDD_ANA2) 41(NC) 42(NC) 45(NC) 53(NC) 54(NC)

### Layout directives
net class 50 OHM: ANT_LEG, CC_RF_OUT, RF_FL_O, SMA_LEG, SMA_OUT

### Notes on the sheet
- RF Output
- CC3100MOD Wi-Fi Subsystem
- (near J10) CC3100 Programming Connector
- Text String

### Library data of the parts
C17 = GRM1555C1H100JA01D: CAP, CERM, 10 pF, 50 V, +/- 5%, C0G/NP0, 0402; Manufacturer: MuRata; Polarized: N; CompType: Capacitor; Value: 10pF; U/M: EA; Cap_F: 0.00000000001; Tolerance_%: 5; Value1: Unknown; VDC_V: 50; Value2: 50V; TaMin_C: -55; TaMax_C: 125; Cap_Case: 0402
C18 C19 = GRM1555C1H1R0BA01D: CAP, CERM, 1 pF, 50 V, +/- 10%, C0G/NP0, 0402; Manufacturer: MuRata; Polarized: N; CompType: Capacitor; Value: 1pF; U/M: EA; Cap_F: 0.000000000001; Tolerance_%: 10; Value1: Unknown; VDC_V: 50; Value2: 50V; TaMin_C: -55; TaMax_C: 125; Cap_Case: 0402
C38 C40 = GRM155R60J475ME87D: CAP, CERM, 4.7 µF, 6.3 V, +/- 20%, X5R, 0402; Manufacturer: MuRata; Polarized: N; CompType: Capacitor; Value: 4.7uF; U/M: EA; Cap_F: 0.0000047; Tolerance_%: 20; ESR_ohm: 0.009; Value1: 0.009 ohm; VDC_V: 6.3; IRMS_A: 1.22; TaMin_C: -55; TaMax_C: 85
C39 C42 = GRM155R71C104KA88D: as C6 on sheet ISE4040_TIDA00380_CANtoWiFi_Sheet3
D8 D9 D15 D16 = TPD1E10B06DPYR: as D4 on sheet ISE4040_TIDA00380_CANtoWiFi_Sheet3
E1 = AH316M245001-T: ANT BLUETOOTH W-LAN ZIGBEE WIMAX, SMD; Manufacturer: Taiyo Yuden; SymbolCreator: a0411947; CompType: Antenna
J4 = MM8030-2610RJ3: Coaxial Connectors with Switch, 50 Ohm, SMD; Manufacturer: MuRata; SymbolCreator: Altium; U/M: EA
J6 = 5-1814832-1: SMA Straight PCB Socket Die Cast, 50 Ohm, TH; SymbolCreator: X0208326; CompType: JACK; U/M: EA
J10 = PBC03SAAN: as J5 on sheet ISE4040_TIDA00380_CANtoWiFi_Sheet3
J11 = PBC02SAAN: Header, 100mil, 2x1, Gold, TH; Manufacturer: Sullins Connector Solutions; SymbolCreator: a0412235; U/M: EA
L3 = LQG15HS3N6S02D: Inductor, Multilayer, Air Core, 3.6 nH, 0.3 A, 0.18 ohm, SMD; Manufacturer: MuRata; Ind_H: 3.6E-9; Imax_A: 0.3; Irms: 0.3A @ C rise; Isat: 0.3A @ % inductance drop; DCR_ohm: 0.18; Value2: 0.3A
L4 = LQP15MN3N6B02D: Inductor, Film, 3.6 nH, 0.17 A, 0.5 ohm, SMD; Manufacturer: MuRata; Ind_H: 3.6E-9; Imax_A: 0.17; DCR_ohm: 0.5; Value1: 0.5 ohm; Value2: 0.17A
R13 R15 = CRCW04020000Z0ED: as R2 on sheet ISE4040_TIDA00380_CANtoWiFi_Sheet3
R20 R22-R26 R30 = CRCW0402100KFKED: as R29 on sheet ISE4040_TIDA00380_CANtoWiFi_Sheet3
R27 = CRCW04022K67FKED: RES, 2.67 k, 1%, 0.063 W, 0402; Manufacturer: Vishay-Dale; CompType: Resistor; Value: 2.67k; Res_ohm: 2670; Value_Code: 2k67; Tolerance_%: 1; Power_W: 0.063; Value2: 0.063W; VDC_V: 50; TempCo: 100 ppm/C; EIA_Code: E96; U/M: EA
R28 = CRCW0402270RJNED: RES, 270, 5%, 0.063 W, 0402; Manufacturer: Vishay-Dale; CompType: Resistor; Value: 270; Value_Code: 270R; Tolerance_%: 5; Power_W: 0.063; Value2: 0.063W; VDC_V: 50; TempCo: 200 ppm/C; EIA_Code: E24; U/M: EA
S2 = B3U-1000P: as S1 on sheet ISE4040_TIDA00380_CANtoWiFi_Sheet3
SH-J11 = 2SN-BK-G: as SH-J2 on sheet ISE4040_TIDA00380_CANtoWiFi_Sheet2
TP6-TP10 = PogoPad: Pad for Pogo Pin Connector; SymbolCreator: codlsc
U4 = CC3100MODR11MAMOBR: SimpleLink™ Certified Wi-Fi® Network Processor Internet-of-Things Module Solution for MCU Applications, MOB0063A; Alternate PartNumber: CC3100MODR11MAMOBT; Manufacturer: Texas Instruments; SymbolCreator: Altium; CompType: IC; U/M: EA

## Sheet ISE4040_TIDA00380_CANtoWiFi_Sheet5.SchDoc
size 431 x 279 mm; Date: Not shown in title block; ApprovedBy: Not shown in title block; CheckedBy: Not shown in title block; Author: Not shown in title block; CompanyName: Not shown in title block; Engineer: Not shown in title block; Organization: Not shown in title block; Address1: Not shown in title block; Address2: Not shown in title block; Address3: Not shown in title block; Address4: Not shown in title block; DocumentNumber: 5; Revision: Use project parameter SCH_Rev; SheetNumber: 5; SheetTotal: 5; PageSetup: Record=PageOptions¦CenterHorizontal=True¦CenterVertical=True¦PrintScale=1.00¦XCorrection=1.00¦YCorrection=1.00¦PrintKind=0¦BorderSize=5000000¦LeftOffset=0¦BottomOffset=0¦Orientation=2¦PaperLength=1000¦PaperWidth=1000¦Scale=100¦PaperSource=15¦PrintQuality=600¦MediaType=1¦DitherType=10¦PaperKind=Letter¦PrintScaleMode=1
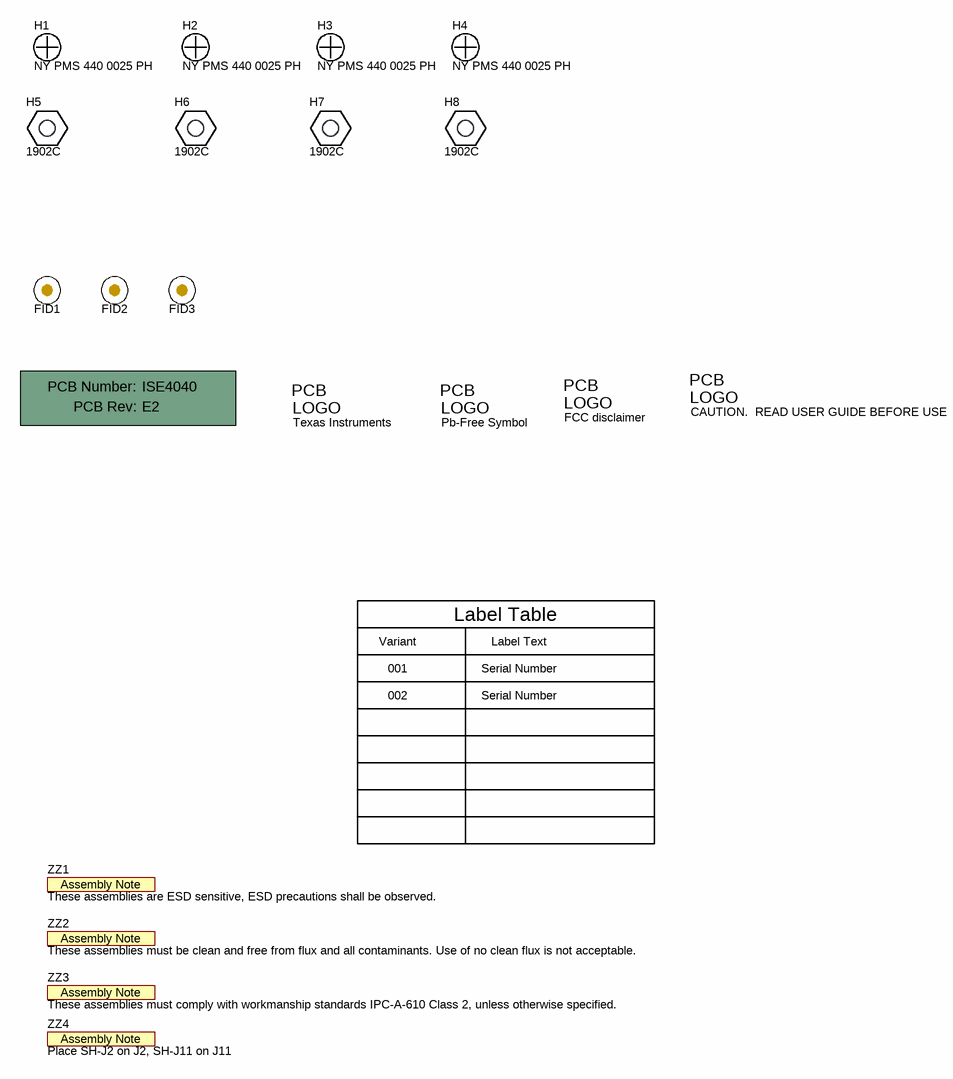
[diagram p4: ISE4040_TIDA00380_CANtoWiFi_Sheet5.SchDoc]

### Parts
!PCB  Printed Circuit Board  (value not drawn)  (mechanical)
FID1  Fiducial  [Fiducial10-20]  (value not drawn)
FID2  Fiducial  [Fiducial10-20]  (value not drawn)
FID3  Fiducial  [Fiducial10-20]  (value not drawn)
H1  NY PMS 440 0025 PH  [NY PMS 440 0025 PH]
H2  NY PMS 440 0025 PH  [NY PMS 440 0025 PH]
H3  NY PMS 440 0025 PH  [NY PMS 440 0025 PH]
H4  NY PMS 440 0025 PH  [NY PMS 440 0025 PH]
H5  1902C  [Keystone_1902C]
H6  1902C  [Keystone_1902C]
H7  1902C  [Keystone_1902C]
H8  1902C  [Keystone_1902C]
Logo1  Texas Instruments  [TI_Stacked_Overlay_Medium]  (no BOM)
Logo2  Pb-Free Symbol  [Pb-Free_Overlay_Small]  (no BOM)
Logo3  CAUTION.  READ USER GUIDE BEFORE USE  [IEC_Caution_Small]  (no BOM)
Logo4  FCC disclaimer  [FCC_disclaimer_stacked]  (no BOM)
ZZ1  These assemblies are ESD sensitive, ESD precautions shall be observed.  [AssemblyNote]  (no BOM)
ZZ2  These assemblies must be clean and free from flux and all contaminants. Use of no clean flux is not acceptable.  [AssemblyNote]  (no BOM)
ZZ3  These assemblies must comply with workmanship standards IPC-A-610 Class 2, unless otherwise specified.  [AssemblyNote]  (no BOM)
ZZ4  Place SH-J2 on J2, SH-J11 on J11  [AssemblyNote]  (no BOM)

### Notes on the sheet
- Variant
- Label Table
- Label Text
- 001
- 002
- Serial Number

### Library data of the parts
!PCB = PCB: Manufacturer: Any; PartNumber: ISE4040; SymbolCreator: a0412235
FID1-FID3 = Fiducial: Fiducial mark.  There is nothing to buy or mount.; SymbolCreator: codlsc
H1-H4 = NY PMS 440 0025 PH: Machine Screw, Round, #4-40 x 1/4, Nylon, Philips panhead; Manufacturer: B&F Fastener Supply; CompType: Hardware; SymbolCreator: codlsc; U/M: EA
H5-H8 = 1902C: Standoff, Hex, 0.5"L #4-40 Nylon; Manufacturer: Keystone; CompType: Hardware
Logo1 = TI_Logo: Texas Instrument Corporate Signature; SymbolCreator: codlsc
Logo2 = Pb-Free: SymbolCreator: a0412235
Logo3 = IEC_Caution: IEC 61010-1 Caution Warning; SymbolCreator: a0412235
Logo4 = FCC_disclaimer: SymbolCreator: codlsc
ZZ1-ZZ4 = AssemblyNote: SymbolCreator: codlsc

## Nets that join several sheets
3V3: ISE4040_TIDA00380_CANtoWiFi_Sheet2 (D5.1 R1.2), ISE4040_TIDA00380_CANtoWiFi_Sheet3 (17 pins), ISE4040_TIDA00380_CANtoWiFi_Sheet4 (10 pins)
5V: ISE4040_TIDA00380_CANtoWiFi_Sheet2 (5 pins), ISE4040_TIDA00380_CANtoWiFi_Sheet3 (R2.2)
GND: ISE4040_TIDA00380_CANtoWiFi_Sheet2 (18 pins), ISE4040_TIDA00380_CANtoWiFi_Sheet3 (45 pins), ISE4040_TIDA00380_CANtoWiFi_Sheet4 (46 pins)
VBUS: ISE4040_TIDA00380_CANtoWiFi_Sheet2 (5 pins), ISE4040_TIDA00380_CANtoWiFi_Sheet3 (C23.1 U3.46)
CC_HIB: ISE4040_TIDA00380_CANtoWiFi_Sheet3 (U3.23), ISE4040_TIDA00380_CANtoWiFi_Sheet4 (U4.4)
CC_INT: ISE4040_TIDA00380_CANtoWiFi_Sheet3 (U3.24), ISE4040_TIDA00380_CANtoWiFi_Sheet4 (U4.11)
CS_CC: ISE4040_TIDA00380_CANtoWiFi_Sheet3 (U3.20), ISE4040_TIDA00380_CANtoWiFi_Sheet4 (U4.8)
MOSI_CC: ISE4040_TIDA00380_CANtoWiFi_Sheet3 (U3.22), ISE4040_TIDA00380_CANtoWiFi_Sheet4 (U4.6)
nRST_CC: ISE4040_TIDA00380_CANtoWiFi_Sheet3 (U3.16), ISE4040_TIDA00380_CANtoWiFi_Sheet4 (5 pins)
SCLK_CC: ISE4040_TIDA00380_CANtoWiFi_Sheet3 (U3.19), ISE4040_TIDA00380_CANtoWiFi_Sheet4 (U4.5)
SOMI_CC: ISE4040_TIDA00380_CANtoWiFi_Sheet3 (U3.21), ISE4040_TIDA00380_CANtoWiFi_Sheet4 (U4.7)
USB_D_N: ISE4040_TIDA00380_CANtoWiFi_Sheet2 (J1.2 U2.5), ISE4040_TIDA00380_CANtoWiFi_Sheet3 (U3.43)
USB_D_P: ISE4040_TIDA00380_CANtoWiFi_Sheet2 (J1.3 U2.3), ISE4040_TIDA00380_CANtoWiFi_Sheet3 (U3.44)

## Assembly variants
001: not fitted C17 C19 FID1 FID2 FID3 J6 L3 R13 R24 R29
